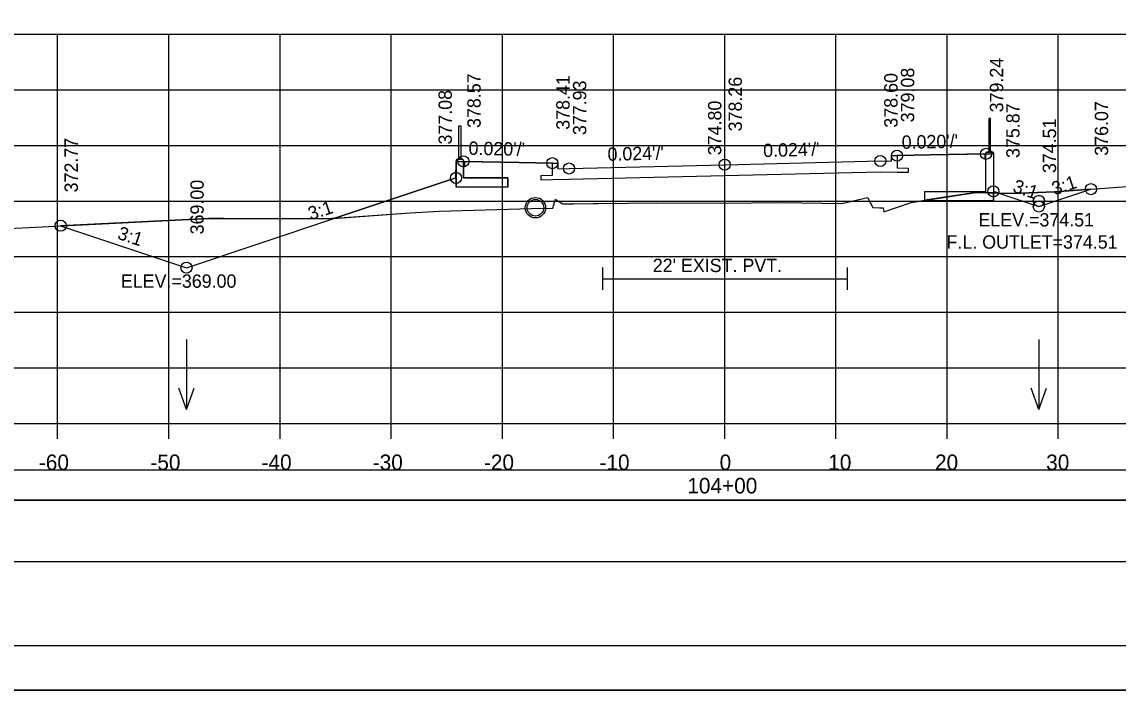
# Model space of a CAD drawing. Extents: x -37291014 to -37290680, y -936053 to -933067.
# Drawn here: x -37290906.3 to -37290807.7, y -935200 to -935139.9 of the extents above; entities that cross this region are included whole.
import ezdxf

# ---------------------------------------------------------------- set-up
doc = ezdxf.new("R2010")
doc.units = 0
for name, color, linetype in [('Default', 7, 'Continuous'), ('R_Alt Surface', 7, 'Continuous'), ('R_Axis', 7, 'Continuous'), ('R_Axis Annot', 7, 'Continuous'), ('R_Border', 7, 'Continuous'), ('R_Contours', 7, 'Continuous'), ('R_Exist Surface', 7, 'Continuous'), ('R_Fin Surface', 7, 'Continuous'), ('R_Grid', 7, 'Continuous'), ('R_No Plot', 7, 'Continuous'), ('R_Water', 7, 'Continuous'), ('R_Water Annot', 7, 'Continuous'), ('R_Xsect Elev', 7, 'Continuous'), ('R_Xsect Slope', 7, 'Continuous')]:
    doc.layers.add(name, color=color, linetype=linetype)

msp = doc.modelspace()

# ---------------------------------------------------------------- linework, layer by layer
at = {"layer": 'Default'}
for p, q in [((-37290819.352, -935148.544), (-37290819.352, -935151.544)), ((-37290819.185, -935148.544), (-37290819.352, -935148.544)), ((-37290819.185, -935151.544), (-37290819.185, -935148.544)), ((-37290867.018, -935152.216), (-37290867.018, -935149.216)), ((-37290867.018, -935149.216), (-37290866.852, -935149.216)), ((-37290866.852, -935149.216), (-37290866.852, -935152.216)), ((-37290819.602, -935151.628), (-37290819.539, -935151.565)), ((-37290819.602, -935155.102), (-37290819.602, -935151.628)), ((-37290819.539, -935151.544), (-37290818.997, -935151.544)), ((-37290819.539, -935151.565), (-37290819.539, -935151.544)), ((-37290819.539, -935151.565), (-37290818.997, -935151.565)), ((-37290818.997, -935151.544), (-37290818.997, -935151.565)), ((-37290818.997, -935151.565), (-37290818.935, -935151.628)), ((-37290818.935, -935151.628), (-37290818.935, -935155.935)), ((-37290867.206, -935152.237), (-37290867.268, -935152.3)), ((-37290867.268, -935152.3), (-37290867.268, -935154.725)), ((-37290866.664, -935152.216), (-37290867.206, -935152.216)), ((-37290867.206, -935152.216), (-37290867.206, -935152.237)), ((-37290866.664, -935152.237), (-37290867.206, -935152.237)), ((-37290866.664, -935152.237), (-37290866.664, -935152.216)), ((-37290866.602, -935152.3), (-37290866.664, -935152.237)), ((-37290866.602, -935153.892), (-37290866.602, -935152.3)), ((-37290862.598, -935153.892), (-37290866.602, -935153.892)), ((-37290862.598, -935154.725), (-37290862.598, -935153.892)), ((-37290862.598, -935154.725), (-37290867.268, -935154.725)), ((-37290825.105, -935155.935), (-37290825.105, -935155.102)), ((-37290825.105, -935155.102), (-37290819.602, -935155.102)), ((-37290825.105, -935155.935), (-37290818.935, -935155.935))]:
    msp.add_line(p, q, dxfattribs=at)
for points in [[(-37290866.518, -935152.904), (-37290866.602, -935152.904), (-37290866.602, -935152.404), (-37290866.518, -935152.404), (-37290866.518, -935152.904)], [(-37290819.685, -935152.232), (-37290819.602, -935152.232), (-37290819.602, -935151.732), (-37290819.685, -935151.732), (-37290819.685, -935152.232)]]:
    msp.add_lwpolyline(points, dxfattribs=at)
for points in [[(-37290992.481, -935182.878), (-37290693.722, -935182.878), (-37290693.722, -935180.172), (-37290992.481, -935180.172)], [(-37290992.481, -935188.4), (-37290693.722, -935188.4), (-37290693.722, -935182.878), (-37290992.481, -935182.878)]]:
    msp.add_lwpolyline(points, close=True, dxfattribs=at)
at = {"layer": 'R_Alt Surface'}
for points in [[(-37290827.602, -935151.892), (-37290827.602, -935152.985), (-37290826.592, -935153.005), (-37290826.602, -935153.422), (-37290827.602, -935153.402), (-37290829.102, -935153.372), (-37290843.102, -935153.708), (-37290857.102, -935154.044), (-37290858.602, -935154.074), (-37290859.602, -935154.094), (-37290859.612, -935153.677), (-37290858.602, -935153.657), (-37290858.602, -935152.564)], [(-37290854.102, -935161.962), (-37290854.102, -935163.962)], [(-37290832.102, -935161.962), (-37290832.102, -935163.962)], [(-37290854.102, -935162.962), (-37290832.102, -935162.962)]]:
    msp.add_lwpolyline(points, dxfattribs=at)
at = {"layer": 'R_Axis'}
for p, q in [((-37290993.102, -935175.972), (-37290693.102, -935175.972)), ((-37290903.102, -935177.372), (-37290903.102, -935175.972)), ((-37290893.102, -935177.372), (-37290893.102, -935175.972)), ((-37290883.102, -935177.372), (-37290883.102, -935175.972)), ((-37290873.102, -935177.372), (-37290873.102, -935175.972)), ((-37290863.102, -935177.372), (-37290863.102, -935175.972)), ((-37290853.102, -935177.372), (-37290853.102, -935175.972)), ((-37290843.102, -935177.372), (-37290843.102, -935175.972)), ((-37290833.102, -935177.372), (-37290833.102, -935175.972)), ((-37290823.102, -935177.372), (-37290823.102, -935175.972)), ((-37290813.102, -935177.372), (-37290813.102, -935175.972))]:
    msp.add_line(p, q, dxfattribs=at)
at = {"layer": 'R_Border'}
msp.add_line((-37290684.921, -935195.972), (-37291001.102, -935195.972), dxfattribs=at)
at = {"layer": 'R_Contours'}
for p, q in [((-37290819.602, -935155.102), (-37290819.602, -935152.232)), ((-37290866.602, -935152.904), (-37290866.602, -935153.892)), ((-37290867.273, -935153.892), (-37290878.166, -935157.523)), ((-37290867.268, -935154.725), (-37290867.268, -935153.892)), ((-37290866.602, -935153.892), (-37290862.598, -935153.892)), ((-37290862.598, -935153.892), (-37290862.598, -935154.725)), ((-37290862.598, -935154.725), (-37290867.268, -935154.725)), ((-37290825.105, -935155.907), (-37290825.105, -935155.102)), ((-37290825.105, -935155.102), (-37290819.602, -935155.102)), ((-37290818.935, -935155.102), (-37290818.935, -935155.25)), ((-37290818.935, -935155.935), (-37290818.935, -935155.25)), ((-37290818.935, -935155.25), (-37290818.44, -935155.265)), ((-37290818.44, -935155.265), (-37290818.931, -935155.102)), ((-37290810.164, -935154.903), (-37290813.401, -935155.141)), ((-37290825.105, -935155.907), (-37290825.105, -935155.935)), ((-37290825.105, -935155.935), (-37290818.935, -935155.935)), ((-37290878.166, -935157.523), (-37290878.745, -935157.564))]:
    msp.add_line(p, q, dxfattribs=at)
for points in [[(-37290866.518, -935152.406), (-37290866.518, -935152.904), (-37290866.602, -935152.904)], [(-37290858.602, -935152.564), (-37290861.602, -935152.504), (-37290866.518, -935152.406)], [(-37290827.602, -935151.892), (-37290827.602, -935152.985), (-37290826.592, -935153.005), (-37290826.602, -935153.422), (-37290827.602, -935153.402), (-37290829.102, -935153.372), (-37290843.102, -935153.708), (-37290857.102, -935154.044), (-37290858.602, -935154.074), (-37290859.602, -935154.094), (-37290859.612, -935153.677), (-37290858.602, -935153.657), (-37290858.602, -935152.564)], [(-37290819.685, -935151.734), (-37290824.602, -935151.832), (-37290827.602, -935151.892)], [(-37290819.602, -935152.232), (-37290819.685, -935152.232), (-37290819.685, -935151.734)], [(-37290867.268, -935153.892), (-37290867.273, -935153.892)], [(-37290818.935, -935155.25), (-37290820.519, -935155.201), (-37290825.105, -935155.907)], [(-37290818.931, -935155.102), (-37290818.935, -935155.102)], [(-37290818.44, -935155.265), (-37290814.845, -935156.463), (-37290810.164, -935154.903)], [(-37290813.401, -935155.141), (-37290817.251, -935155.303), (-37290818.44, -935155.265)], [(-37290878.166, -935157.523), (-37290871.384, -935157.034), (-37290868.78, -935156.887), (-37290860.495, -935156.657), (-37290858.572, -935156.613), (-37290858.487, -935156.302), (-37290858.332, -935155.811), (-37290858.176, -935155.927), (-37290857.672, -935156.224), (-37290856.691, -935156.225), (-37290854.945, -935156.197), (-37290854.494, -935156.209), (-37290849.209, -935156.139), (-37290843.52, -935156.172), (-37290837.97, -935156.105), (-37290832.56, -935156.181), (-37290830.265, -935155.665), (-37290829.776, -935156.563), (-37290829.17, -935156.585), (-37290828.85, -935156.581), (-37290828.8, -935156.936), (-37290826.325, -935156.095), (-37290825.105, -935155.907)], [(-37290902.837, -935158.198), (-37290891.515, -935161.972), (-37290878.166, -935157.523)], [(-37290878.745, -935157.564), (-37290888.157, -935157.536), (-37290889.541, -935157.531), (-37290891.927, -935157.65), (-37290902.837, -935158.198)]]:
    msp.add_lwpolyline(points, dxfattribs=at)
at = {"layer": 'R_Exist Surface'}
msp.add_lwpolyline([(-37290911.089, -935158.613), (-37290891.927, -935157.65), (-37290889.541, -935157.531), (-37290888.157, -935157.536), (-37290878.745, -935157.564), (-37290871.384, -935157.034), (-37290868.78, -935156.887), (-37290860.495, -935156.657), (-37290858.572, -935156.613), (-37290858.487, -935156.302), (-37290858.332, -935155.811), (-37290858.176, -935155.927), (-37290857.672, -935156.224), (-37290856.691, -935156.225), (-37290854.945, -935156.197), (-37290854.494, -935156.209), (-37290849.209, -935156.139), (-37290843.52, -935156.172), (-37290837.97, -935156.105), (-37290832.56, -935156.181), (-37290830.265, -935155.665), (-37290829.776, -935156.563), (-37290829.17, -935156.585), (-37290828.85, -935156.581), (-37290828.8, -935156.936), (-37290826.325, -935156.095), (-37290820.519, -935155.201), (-37290817.251, -935155.303), (-37290813.401, -935155.141), (-37290800.435, -935154.189)], dxfattribs=at)
at = {"layer": 'R_Fin Surface'}
msp.add_lwpolyline([(-37290902.837, -935158.198), (-37290891.515, -935161.972), (-37290878.166, -935157.523), (-37290867.273, -935153.892), (-37290867.272, -935152.404), (-37290866.602, -935152.404), (-37290861.602, -935152.504), (-37290858.602, -935152.564), (-37290858.102, -935152.564), (-37290858.101, -935153.064), (-37290857.102, -935153.044), (-37290843.102, -935152.708), (-37290829.102, -935152.372), (-37290828.103, -935152.392), (-37290828.102, -935151.892), (-37290827.602, -935151.892), (-37290824.602, -935151.832), (-37290819.602, -935151.732), (-37290818.932, -935151.732), (-37290818.931, -935155.102), (-37290818.44, -935155.265), (-37290814.845, -935156.463), (-37290810.164, -935154.903)], dxfattribs=at)
at = {"layer": 'R_Grid'}
for p, q in [((-37290993.102, -935140.972), (-37290693.102, -935140.972)), ((-37290903.102, -935175.972), (-37290903.102, -935140.972)), ((-37290893.102, -935175.972), (-37290893.102, -935140.972)), ((-37290883.102, -935175.972), (-37290883.102, -935140.972)), ((-37290873.102, -935175.972), (-37290873.102, -935140.972)), ((-37290863.102, -935175.972), (-37290863.102, -935140.972)), ((-37290853.102, -935175.972), (-37290853.102, -935140.972)), ((-37290843.102, -935175.972), (-37290843.102, -935140.972)), ((-37290833.102, -935175.972), (-37290833.102, -935140.972)), ((-37290823.102, -935175.972), (-37290823.102, -935140.972)), ((-37290813.102, -935175.972), (-37290813.102, -935140.972)), ((-37290993.102, -935145.972), (-37290693.102, -935145.972)), ((-37290993.102, -935150.972), (-37290693.102, -935150.972)), ((-37290993.102, -935155.972), (-37290693.102, -935155.972)), ((-37290993.102, -935160.972), (-37290693.102, -935160.972)), ((-37290993.102, -935165.972), (-37290693.102, -935165.972)), ((-37290993.102, -935170.972), (-37290693.102, -935170.972)), ((-37290993.102, -935175.972), (-37290693.102, -935175.972))]:
    msp.add_line(p, q, dxfattribs=at)
at = {"layer": 'R_No Plot'}
msp.add_line((-37291013.502, -935199.95), (-37290680.169, -935199.95), dxfattribs=at)
for points in [[(-37291013.509, -934986.617), (-37290680.169, -934986.617), (-37290680.169, -935199.955), (-37291013.509, -935199.955)], [(-37290767.182, -934990.512), (-37290747.562, -934990.512), (-37290747.562, -935000.392), (-37290731.449, -935000.392), (-37290708.25, -935000.392), (-37290708.25, -935024.724), (-37290684.921, -935024.724), (-37290684.921, -935195.972), (-37291001.102, -935195.972), (-37291001.102, -934990.512)]]:
    msp.add_lwpolyline(points, close=True, dxfattribs=at)
for centre, radius in [((-37290827.602, -935151.892), 0.5), ((-37290819.602, -935151.732), 0.5), ((-37290866.602, -935152.404), 0.5), ((-37290858.602, -935152.564), 0.5), ((-37290857.102, -935153.044), 0.5), ((-37290843.102, -935152.708), 0.5), ((-37290829.102, -935152.372), 0.5), ((-37290829.102, -935152.372), 0.5), ((-37290867.273, -935153.892), 0.5), ((-37290818.931, -935155.102), 0.5), ((-37290810.164, -935154.903), 0.5), ((-37290814.845, -935155.963), 0.505), ((-37290860.13, -935156.573), 0.917), ((-37290814.845, -935156.463), 0.5), ((-37290902.837, -935158.198), 0.5), ((-37290891.515, -935161.972), 0.5)]:
    msp.add_circle(centre, radius, dxfattribs=at)
at = {"layer": 'R_Water'}
for centre, radius in [((-37290814.845, -935155.963), 0.5), ((-37290860.13, -935156.573), 0.75)]:
    msp.add_circle(centre, radius, dxfattribs=at)
at = {"layer": 'R_Water Annot'}
for p, q in [((-37290891.515, -935168.429), (-37290891.515, -935174.713)), ((-37290814.845, -935168.429), (-37290814.845, -935174.713)), ((-37290891.515, -935174.713), (-37290892.215, -935172.79)), ((-37290891.515, -935174.713), (-37290890.815, -935172.79)), ((-37290814.845, -935174.713), (-37290815.545, -935172.79)), ((-37290814.845, -935174.713), (-37290814.145, -935172.79))]:
    msp.add_line(p, q, dxfattribs=at)
at = {"layer": 'R_Xsect Elev'}
msp.add_line((-37290843.102, -935156.167), (-37290843.102, -935144.856), dxfattribs=at)

# ---------------------------------------------------------------- texts
at = {"layer": 'R_Axis Annot'}
for s, p in [('-60', (-37290904.794, -935180.172)), ('-50', (-37290894.761, -935180.172)), ('-40', (-37290884.761, -935180.172)), ('-30', (-37290874.761, -935180.172)), ('-20', (-37290864.761, -935180.172)), ('-10', (-37290854.364, -935180.172)), ('0', (-37290843.559, -935180.172)), ('10', (-37290833.791, -935180.172)), ('20', (-37290824.187, -935180.172)), ('30', (-37290814.187, -935180.172)), ('104+00', (-37290846.469, -935182.272))]:
    msp.add_text(s, height=1.4, dxfattribs=at).set_placement(p)
at = {"layer": 'R_Water'}
msp.add_text("22' EXIST. PVT.", height=1.2, dxfattribs=at).set_placement((-37290849.575, -935162.362))
at = {"layer": 'R_Water Annot'}
msp.add_text('F.L. OUTLET=374.51', height=1.2, dxfattribs=at).set_placement((-37290823.151, -935160.258))
at = {"layer": 'R_Xsect Elev'}
for s, p in [('379.24', (-37290818.052, -935147.997)), ('378.57', (-37290865.052, -935149.404)), ('378.41', (-37290857.052, -935149.564)), ('378.60', (-37290827.552, -935149.372)), ('378.60', (-37290827.552, -935149.372)), ('379.08', (-37290826.052, -935148.892)), ('377.93', (-37290855.552, -935150.044)), ('378.26', (-37290841.552, -935149.708)), ('377.08', (-37290867.646, -935150.892)), ('374.80', (-37290843.402, -935151.856)), ('375.87', (-37290816.578, -935152.102)), ('376.07', (-37290808.614, -935151.903)), ('374.51', (-37290813.295, -935153.463)), ('372.77', (-37290901.287, -935155.198)), ('369.00', (-37290889.965, -935158.972))]:
    msp.add_text(s, height=1.2, rotation=90, dxfattribs=at).set_placement(p)
for s, p in [('ELEV.=374.51', (-37290820.279, -935158.263)), ('ELEV.=369.00', (-37290897.416, -935163.772))]:
    msp.add_text(s, height=1.2, dxfattribs=at).set_placement(p)
at = {"layer": 'R_Xsect Slope'}
for s, rotation, p in [("0.020'/'", 358.85424, (-37290866.151, -935151.813)), ("0.024'/'", 1.37483, (-37290839.63, -935152.024)), ("0.020'/'", 1.14576, (-37290827.175, -935151.283)), ("0.024'/'", 1.37483, (-37290853.63, -935152.36)), ('3:1', 341.56677, (-37290817.273, -935155.127)), ('3:1', 18.43323, (-37290813.452, -935155.472)), ('3:1', 18.43323, (-37290880.341, -935157.72)), ('3:1', 341.56677, (-37290897.807, -935159.348))]:
    msp.add_text(s, height=1.2, rotation=rotation, dxfattribs=at).set_placement(p)

doc.saveas('drawing.dxf')
